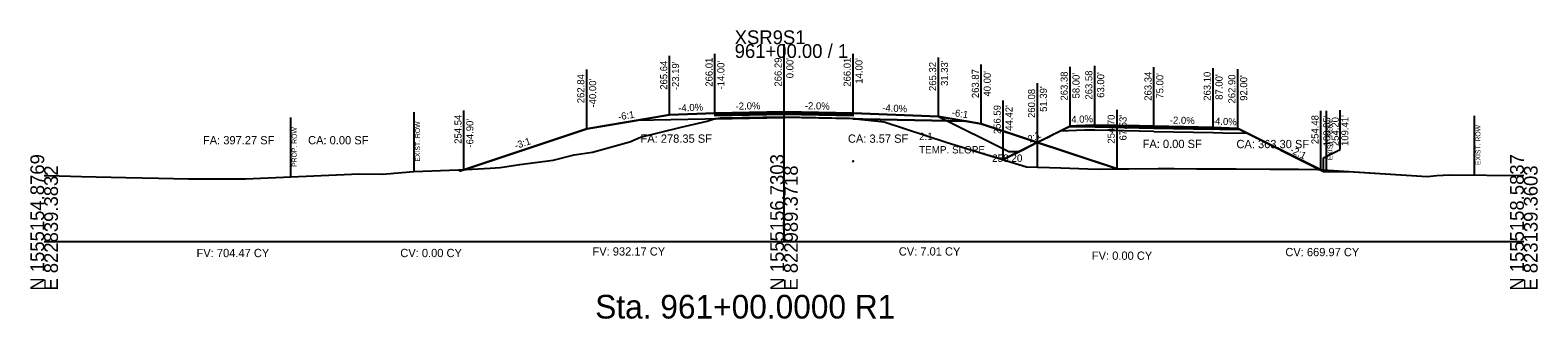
# Model space of a CAD drawing. Extents: x -26 to 823017, y -16 to 1558356.
# Drawn here: x 997.2 to 1302.8, y -15.7 to 42.8 of the extents above; entities that cross this region are included whole.
import ezdxf

# ---------------------------------------------------------------- set-up
doc = ezdxf.new("R2010")
doc.units = 0
for name, color, linetype in [('ASPHALT_19MM1', 7, 'Continuous'), ('ASPHALT_9_5MM1', 7, 'Continuous'), ('CONST_DCH', 7, 'Continuous'), ('CONST_LV3', 7, 'Continuous'), ('Default', 7, 'Continuous'), ('Draft_XS_Grid', 7, 'Continuous'), ('Draft_XS_Text', 7, 'Continuous'), ('DTM_CORRIDOR', 7, 'Continuous'), ('DTM_P_FINISHED_GRADE2', 7, 'Continuous'), ('DTM_TEMP_DROP', 7, 'Continuous'), ('DTM_X_GROUND', 7, 'Continuous'), ('PROFILES_DCH_2', 7, 'Continuous'), ('SLOPE_STAKES_FILL', 7, 'Continuous'), ('XS_CELL', 7, 'Continuous'), ('XS_M_SHAPES_EARTHWORK', 7, 'Continuous'), ('XS_P_ASPHALT', 7, 'Continuous'), ('XS_P_DR_GRAVEL', 7, 'Continuous'), ('XS_P_GROUND', 7, 'Continuous'), ('XS_P_NULL_POINT', 7, 'Continuous'), ('XS_P_ROW', 7, 'Continuous'), ('XS_P_SHOULDER', 7, 'Continuous'), ('XS_P_SUBGRADE_GRANULAR', 7, 'Continuous'), ('XS_P_SUBGRADE_MILLING', 7, 'Continuous'), ('XS_P_SUBGRADE_UNDERCUT', 7, 'Continuous'), ('XS_P_TX_CLEARZONE', 7, 'Continuous'), ('XS_P_TX_FS_BS', 7, 'Continuous'), ('XS_SHEET_EW_TX_AREA', 7, 'Continuous'), ('XS_SHEET_EW_TX_VOLUME', 7, 'Continuous'), ('XS_SHEET_LABELS_ELEVATION', 7, 'Continuous'), ('XS_X_ROW', 7, 'Continuous')]:
    doc.layers.add(name, color=color, linetype=linetype)

msp = doc.modelspace()

# ---------------------------------------------------------------- linework, layer by layer
at = {"layer": 'ASPHALT_19MM1'}
for points in [[(1136, 25.72), (1136, 25.51), (1150, 25.79), (1150, 25.79), (1150, 25.79), (1164, 25.51), (1164, 25.72), (1164, 25.72), (1150, 26), (1150, 26), (1150, 26), (1136, 25.72), (1136, 25.72)], [(1213, 23.21), (1225, 22.97), (1237, 22.73), (1237, 22.94), (1225, 23.18), (1213, 23.42), (1213, 23.21)]]:
    msp.add_lwpolyline(points, dxfattribs=at)
at = {"layer": 'ASPHALT_9_5MM1'}
msp.add_lwpolyline([(1136, 26.01), (1136, 25.89), (1150, 26.17), (1150, 26.17), (1150, 26.17), (1164, 25.89), (1164, 26.01), (1164, 26.01), (1150, 26.29), (1150, 26.29), (1150, 26.29), (1136, 26.01), (1136, 26.01)], dxfattribs=at)
at = {"layer": 'CONST_DCH'}
msp.add_lwpolyline([(1213, 23.42), (1225, 23.18), (1237, 22.94), (1237, 23.1), (1225, 23.34), (1213, 23.58), (1213, 23.42)], dxfattribs=at)
at = {"layer": 'CONST_LV3'}
for points in [[(1110, 22.84), (1110, 22.84), (1120.11, 24.53)], [(1150, 26.29), (1164, 26.01)], [(1181.33, 25.32), (1181.33, 25.32), (1164, 26.01)], [(1190, 23.87), (1190, 23.87), (1186.92, 24.39)], [(1194.42, 16.59), (1204.8, 21.78), (1208, 23.38), (1211.75, 23.53), (1213, 23.58)], [(1201.39, 20.08), (1201.42, 20.09), (1203.67, 21.22), (1204.46, 21.61), (1204.8, 21.78), (1205.55, 22.16), (1208, 23.38), (1209.25, 23.43), (1213, 23.58), (1222.01, 23.4), (1225, 23.34), (1234.01, 23.16), (1237, 23.1), (1240.75, 22.95), (1242, 22.9), (1246.15, 20.83), (1251.38, 18.21), (1257.12, 15.34), (1259.41, 14.2), (1265.44, 14.12), (1280.4, 13.18), (1282.33, 13.33), (1284.96, 13.52), (1300, 13.39)], [(1242, 22.9), (1258.85, 14.48)], [(1164, 16.06), (1164, 16.3), (1164, 16.24), (1164, 16.18), (1164, 16.18), (1164, 16.18), (1164, 16.18)], [(1000, 13.37), (1000.78, 13.37), (1007.55, 13.13), (1016.59, 12.94), (1023.15, 12.81), (1029.26, 12.71), (1034.76, 12.71), (1040.83, 12.71), (1063.85, 13.72), (1068.63, 13.65), (1069.41, 13.72), (1074.93, 14.18), (1082.17, 14.44), (1083.98, 14.51), (1084.36, 14.52), (1084.4, 14.52), (1084.58, 14.52), (1085.1, 14.54)]]:
    msp.add_lwpolyline(points, dxfattribs=at)
at = {"layer": 'Default'}
msp.add_lwpolyline([(1136, 25.89), (1136, 25.72), (1150, 26), (1150, 26), (1150, 26), (1164, 25.72), (1164, 25.89), (1164, 25.89), (1150, 26.17), (1150, 26.17), (1150, 26.17), (1136, 25.89), (1136, 25.89)], dxfattribs=at)
at = {"layer": 'DTM_P_FINISHED_GRADE2'}
msp.add_lwpolyline([(1085.1, 14.54), (1085.1, 14.54), (1110, 22.84), (1126.81, 25.64), (1136, 26.01), (1150, 26.29), (1164, 26.01), (1181.33, 25.32), (1190, 23.87), (1201.39, 20.08)], dxfattribs=at)
at = {"layer": 'DTM_X_GROUND'}
for points in [[(1000, 13.37), (1000.78, 13.37), (1007.55, 13.13), (1016.59, 12.94), (1023.15, 12.81), (1029.26, 12.71), (1034.76, 12.71), (1040.83, 12.71), (1063.85, 13.72), (1068.63, 13.65), (1069.41, 13.72), (1074.93, 14.18), (1082.17, 14.42), (1083.98, 14.5), (1084.36, 14.29), (1084.4, 14.31), (1084.58, 14.37), (1085.1, 14.54), (1085.1, 14.54), (1110, 22.84), (1110, 22.84), (1126.81, 25.64), (1126.81, 25.64), (1136, 26.01), (1150, 26.29), (1150, 26.29), (1150, 26.29), (1164, 26.01), (1181.33, 25.32), (1181.33, 25.32), (1190, 23.87), (1190, 23.87), (1201.39, 20.08), (1201.39, 20.08), (1201.42, 20.09), (1203.67, 21.22), (1204.46, 21.61), (1204.8, 21.78), (1205.55, 22.16), (1208, 23.38), (1209.25, 23.43), (1213, 23.58), (1222.01, 23.4), (1225, 23.34), (1234.01, 23.16), (1237, 23.1), (1240.75, 22.95), (1242, 22.9), (1246.15, 20.83), (1251.38, 18.21), (1257.12, 15.34), (1259.41, 14.2), (1265.44, 14.12), (1280.4, 13.18), (1282.33, 13.33), (1284.96, 13.52), (1300, 13.39)], [(1000, 13.37), (1000.78, 13.37), (1007.55, 13.13), (1016.59, 12.94), (1023.15, 12.81), (1029.26, 12.71), (1034.76, 12.71), (1040.83, 12.71), (1063.85, 13.72), (1068.63, 13.65), (1069.41, 13.72), (1074.93, 14.18), (1083.98, 14.51), (1084.58, 14.52), (1085.58, 14.56), (1090.42, 14.85), (1092.46, 14.96), (1096.47, 15.62), (1103.19, 16.48), (1107.43, 17.54), (1111.15, 18.12), (1118.48, 20.14), (1118.73, 20.19), (1120.89, 21.15), (1129.17, 23.13), (1134.43, 24.39), (1135.61, 24.76), (1137.15, 25.03), (1137.35, 25.06), (1149.97, 25.23), (1150.12, 25.23), (1162.93, 24.98), (1163, 24.98), (1163.26, 24.96), (1170.31, 24.23), (1183.08, 20.08), (1184.63, 19.57), (1187.19, 18.79), (1199.14, 15.15), (1206.1, 14.92), (1211.6, 14.73), (1213.98, 14.65), (1225.91, 14.81), (1229.13, 14.77), (1254.32, 14.61), (1258.26, 14.57), (1280.4, 13.18), (1282.33, 13.33), (1284.96, 13.52), (1300, 13.39)], [(1000, 13.37), (1000.78, 13.37), (1007.55, 13.13), (1016.59, 12.94), (1023.15, 12.81), (1029.26, 12.71), (1034.76, 12.71), (1040.83, 12.71), (1063.85, 13.72), (1068.63, 13.65), (1069.41, 13.72), (1074.93, 14.18), (1083.98, 14.51), (1084.58, 14.52), (1085.58, 14.56), (1090.42, 14.85), (1092.46, 14.96), (1096.47, 15.62), (1103.19, 16.48), (1107.43, 17.54), (1111.15, 18.12), (1118.48, 20.14), (1118.73, 20.19), (1120.89, 21.15), (1129.17, 23.13), (1134.43, 24.39), (1135.61, 24.76), (1137.15, 25.03), (1137.35, 25.06), (1149.97, 25.23), (1150.12, 25.23), (1162.93, 24.98), (1163, 24.98), (1163.26, 24.96), (1170.31, 24.23), (1183.08, 20.08), (1184.63, 19.57), (1185.99, 19.16), (1187.19, 18.79), (1194.42, 16.59), (1198.84, 18.8), (1201.42, 20.09), (1203.67, 21.22), (1204.46, 21.61), (1204.8, 21.78), (1208, 23.38), (1209.25, 23.43), (1213, 23.58), (1222.01, 23.4), (1225, 23.34), (1234.01, 23.16), (1237, 23.1), (1240.75, 22.95), (1242, 22.9), (1246.15, 20.83), (1251.38, 18.21), (1257.12, 15.34), (1259.41, 14.2), (1265.44, 14.12), (1280.4, 13.18), (1282.33, 13.33), (1284.96, 13.52), (1300, 13.39)]]:
    msp.add_lwpolyline(points, dxfattribs=at)
at = {"layer": 'XS_CELL'}
for p, q in [((1150, 0), (1150, 40)), ((1000, 0), (1150, 0)), ((1150, 0), (1300, 0))]:
    msp.add_line(p, q, dxfattribs=at)
at = {"layer": 'XS_M_SHAPES_EARTHWORK'}
for points in [[(1085.1, 14.54), (1085.58, 14.56), (1090.42, 14.85), (1092.46, 14.96), (1096.47, 15.62), (1103.19, 16.48), (1107.43, 17.54), (1111.15, 18.12), (1118.48, 20.14), (1118.73, 20.19), (1120.89, 21.15), (1129.17, 23.13), (1134.43, 24.39), (1135.61, 24.76), (1136.09, 24.85), (1136, 24.84), (1134, 24.8), (1120.11, 24.53), (1110, 22.84)], [(1136.09, 24.85), (1137.15, 25.03), (1137.35, 25.06), (1149.97, 25.23), (1150.12, 25.23), (1162.93, 24.98), (1163, 24.98), (1163.26, 24.96), (1164.42, 24.84), (1164, 24.84), (1150, 25.12)], [(1164.42, 24.84), (1170.31, 24.23), (1183.08, 20.08), (1184.63, 19.57), (1187.19, 18.79), (1199.14, 15.15), (1201.39, 15.08), (1201.39, 20.08), (1190, 23.87), (1186.92, 24.39), (1166, 24.8)]]:
    msp.add_lwpolyline(points, close=True, dxfattribs=at)
at = {"layer": 'XS_P_DR_GRAVEL'}
for points in [[(1211.75, 23.53), (1208, 23.38), (1207.96, 23.36), (1207.86, 23.31), (1209.14, 23.28), (1213, 23.21), (1213, 23.49), (1213, 23.58), (1211.75, 23.53)], [(1238.25, 23.05), (1242, 22.9), (1242.14, 22.83), (1242.57, 22.62), (1238.39, 22.7), (1237, 22.73), (1237, 23.01), (1237, 23.1), (1238.25, 23.05)]]:
    msp.add_lwpolyline(points, dxfattribs=at)
at = {"layer": 'XS_P_GROUND'}
for p, q in [((1181.33, 25.32), (1195.56, 18.2)), ((1195.56, 18.2), (1197.64, 18.2))]:
    msp.add_line(p, q, dxfattribs=at)
for points in [[(1126.81, 25.64), (1110, 22.84), (1085.1, 14.54)], [(1201.39, 20.08), (1201.39, 20.08), (1190, 23.87), (1190, 23.87), (1181.33, 25.32)], [(1217.53, 14.7), (1190, 23.87), (1190, 23.87), (1190, 23.87), (1181.33, 25.32)], [(1208, 23.38), (1194.42, 16.59)], [(1242, 22.9), (1259.41, 14.2)], [(1217.53, 14.7), (1217.53, 14.7), (1225.91, 14.81), (1225.91, 14.81), (1229.13, 14.77), (1254.32, 14.61), (1254.32, 14.61), (1258.26, 14.57), (1258.85, 14.53)], [(1217.53, 14.7), (1217.53, 14.7), (1225.91, 14.81), (1225.91, 14.81), (1229.13, 14.77), (1254.32, 14.61), (1254.32, 14.61), (1258.26, 14.57), (1258.85, 14.53)]]:
    msp.add_lwpolyline(points, dxfattribs=at)
at = {"layer": 'XS_P_ROW'}
msp.add_line((1050, 13.11), (1050, 25.11), dxfattribs=at)
at = {"layer": 'XS_P_SHOULDER'}
for points in [[(1136, 26.01), (1126.81, 25.64)], [(1164, 26.01), (1181.33, 25.32)], [(1208, 23.38), (1211.75, 23.53), (1213, 23.58)], [(1242, 22.9), (1238.25, 23.05), (1237, 23.1)]]:
    msp.add_lwpolyline(points, dxfattribs=at)
at = {"layer": 'XS_P_SUBGRADE_GRANULAR'}
for points in [[(1136, 24.84), (1134, 24.8), (1120.11, 24.53)], [(1136, 24.84), (1150, 25.12), (1150, 25.12)], [(1164, 24.84), (1150, 25.12), (1150, 25.12)], [(1164, 24.84), (1166, 24.8), (1186.92, 24.39)], [(1213, 22.54), (1211, 22.58), (1206, 22.38)], [(1225, 22.3), (1213, 22.54)], [(1225, 22.3), (1237, 22.06)], [(1237, 22.06), (1239, 22.02), (1243.96, 21.92)]]:
    msp.add_lwpolyline(points, dxfattribs=at)
at = {"layer": 'XS_P_SUBGRADE_UNDERCUT'}
msp.add_lwpolyline([(1217.59, 14.72), (1225.91, 14.81), (1233.71, 14.74), (1248.47, 14.65), (1258.7, 14.56), (1242, 22.9), (1237, 23.1), (1234.01, 23.16), (1225, 23.34), (1222.01, 23.4), (1213, 23.58), (1209.25, 23.43), (1208, 23.38), (1201.39, 20.08)], close=True, dxfattribs=at)
at = {"layer": 'XS_P_TX_CLEARZONE'}
for p, q in [((1126.81, 25.64), (1126.81, 37.64)), ((1136, 26.01), (1136, 38.01)), ((1150, 26.29), (1150, 38.29)), ((1164, 26.01), (1164, 38.01)), ((1181.33, 25.32), (1181.33, 37.32)), ((1110, 22.84), (1110, 34.84)), ((1190, 23.87), (1190, 35.87)), ((1190, 23.87), (1190, 35.87)), ((1208, 23.38), (1208, 35.38)), ((1213, 23.58), (1213, 35.58)), ((1225, 23.34), (1225, 35.34)), ((1237, 23.1), (1237, 35.1)), ((1242, 22.9), (1242, 34.9)), ((1201.39, 20.08), (1201.39, 32.08)), ((1194.42, 16.59), (1194.42, 28.59)), ((1085.1, 14.54), (1085.1, 26.54)), ((1217.53, 14.7), (1217.53, 26.7)), ((1258.85, 14.48), (1258.85, 26.48)), ((1262.74, 18.66), (1262.74, 26.61)), ((1259.41, 16.91), (1262.74, 18.66)), ((1259.41, 14.2), (1259.41, 16.91))]:
    msp.add_line(p, q, dxfattribs=at)
at = {"layer": 'XS_X_ROW'}
for p, q in [((1075, 14.19), (1075, 26.19)), ((1260, 14.46), (1260, 26.46)), ((1290, 13.48), (1290, 25.48))]:
    msp.add_line(p, q, dxfattribs=at)

# ---------------------------------------------------------------- texts
at = {"layer": 'CONST_DCH'}
for p in [(1194.34, 16.47), (1258.77, 14.36), (1259.34, 14.08)]:
    msp.add_text('X', height=0.24, dxfattribs=at).set_placement(p)
at = {"layer": 'Draft_XS_Grid'}
msp.add_text('-', height=0.0001, dxfattribs=at).set_placement((1000, 0))
at = {"layer": 'Draft_XS_Text'}
msp.add_text('Sta. 961+00.0000 R1', height=4.8, dxfattribs=at).set_placement((1111.72, -15.65))
at = {"layer": 'DTM_CORRIDOR'}
for p in [(1212.92, 23.46), (1224.92, 23.22), (1236.92, 22.98)]:
    msp.add_text('X', height=0.24, dxfattribs=at).set_placement(p)
at = {"layer": 'DTM_TEMP_DROP'}
for p in [(1135.92, 25.89), (1149.92, 26.17), (1163.92, 25.89)]:
    msp.add_text('X', height=0.24, dxfattribs=at).set_placement(p)
at = {"layer": 'PROFILES_DCH_2'}
for p in [(1181.25, 25.2), (1189.92, 23.75), (1217.45, 14.58), (1258.77, 14.36)]:
    msp.add_text('X', height=0.24, dxfattribs=at).set_placement(p)
at = {"layer": 'SLOPE_STAKES_FILL'}
for p in [(1201.31, 19.96), (1085.02, 14.42)]:
    msp.add_text('X', height=0.24, dxfattribs=at).set_placement(p)
at = {"layer": 'XS_CELL'}
for s, p in [('XSR9S1', (1140, 40)), ('961+00.00 / 1', (1140, 37.2))]:
    msp.add_text(s, height=2.8, dxfattribs=at).set_placement(p)
for s, p in [('N 1555154.8769', (1000, -10)), ('N 1555156.7303', (1150, -10)), ('N 1555158.5837', (1300, -10)), ('E 822839.3832', (1002.8, -10)), ('E 822989.3718', (1152.8, -10)), ('E 823139.3603', (1302.8, -10))]:
    msp.add_text(s, height=2.8, rotation=90, dxfattribs=at).set_placement(p)
at = {"layer": 'XS_P_ASPHALT'}
for p in [(1194.34, 16.47), (1259.34, 14.08)]:
    msp.add_text('X', height=0.24, dxfattribs=at).set_placement(p)
at = {"layer": 'XS_P_GROUND'}
for s, p in [('2:1', (1177.38, 20.53)), ('TEMP. SLOPE', (1177.38, 17.83))]:
    msp.add_text(s, height=1.5, dxfattribs=at).set_placement(p)
at = {"layer": 'XS_P_NULL_POINT'}
for p in [(1201.31, 19.96), (1085.02, 14.42)]:
    msp.add_text('X', height=0.24, dxfattribs=at).set_placement(p)
at = {"layer": 'XS_P_ROW'}
msp.add_text('PROP. ROW', height=1, rotation=90, dxfattribs=at).set_placement((1051.2, 15.11))
at = {"layer": 'XS_P_SHOULDER'}
for p in [(1109.92, 22.72), (1189.92, 23.75), (1207.92, 23.26), (1241.92, 22.78)]:
    msp.add_text('X', height=0.24, dxfattribs=at).set_placement(p)
at = {"layer": 'XS_P_SUBGRADE_MILLING'}
for p in [(1126.73, 25.52), (1181.25, 25.2)]:
    msp.add_text('X', height=0.24, dxfattribs=at).set_placement(p)
at = {"layer": 'XS_P_TX_CLEARZONE'}
for s, p in [('266.01', (1135.52, 31.37)), ('266.29', (1149.52, 31.39)), ("0.00'", (1151.92, 33.08)), ('266.01', (1163.52, 31.37)), ("14.00'", (1165.92, 31.98)), ('262.84', (1109.52, 28.02)), ('265.64', (1126.33, 30.75)), ("-23.19'", (1128.73, 30.66)), ("-14.00'", (1137.92, 30.8)), ('265.32', (1180.85, 30.5)), ("31.33'", (1183.25, 31.52)), ('263.87', (1189.52, 29.05)), ("40.00'", (1191.92, 29.37)), ('263.38', (1207.52, 28.56)), ("58.00'", (1209.92, 28.99)), ('263.58', (1212.52, 28.76)), ("63.00'", (1214.92, 29.12)), ('263.34', (1224.52, 28.52)), ("75.00'", (1226.92, 28.95)), ('263.10', (1236.52, 28.52)), ("87.00'", (1238.92, 28.71)), ('262.90', (1241.52, 27.96)), ("-40.00'", (1111.92, 27.16)), ('260.08', (1200.91, 25.03)), ("51.39'", (1203.31, 26.27)), ("92.00'", (1243.92, 28.51)), ('256.59', (1193.94, 21.76)), ("44.42'", (1196.34, 22.43)), ('254.54', (1084.62, 19.79)), ("-64.90'", (1087.02, 19.02)), ('254.70', (1217.05, 19.82)), ("67.53'", (1219.45, 20.46)), ('254.48', (1258.37, 19.72)), ("108.85'", (1260.77, 19.27)), ('254.20', (1262.48, 19.32)), ("109.41'", (1264.43, 19.35))]:
    msp.add_text(s, height=1.44, rotation=90, dxfattribs=at).set_placement(p)
at = {"layer": 'XS_P_TX_FS_BS'}
for s, rotation, p in [('-4.0%', 2.2906, (1128.59, 26.32)), ('-2.0%', 1.1458, (1140.2, 26.7)), ('-2.0%', 358.8542, (1154.22, 26.81)), ('-4.0%', 357.7094, (1169.9, 26.38)), ('-6:1', 9.4642, (1116.48, 24.53)), ('-6:1', 350.5358, (1183.94, 25.49)), ('4.0%', 2.2906, (1208.27, 23.99)), ('-2.0%', 358.8542, (1228.22, 23.88)), ('-4.0%', 357.7094, (1236.73, 23.71)), ('2:1', 26.5651, (1199.85, 19.98)), ('-3:1', 18.4332, (1095.64, 18.69)), ('-2:1', 333.4349, (1252.46, 18.09))]:
    msp.add_text(s, height=1.44, rotation=rotation, dxfattribs=at).set_placement(p)
at = {"layer": 'XS_SHEET_EW_TX_AREA'}
for s, p in [('FA: 278.35 SF', (1120.91, 20)), ('CA: 3.57 SF', (1162.96, 20)), ('FA: 397.27 SF', (1032.19, 19.68)), ('CA: 0.00 SF', (1053.51, 19.68)), ('FA: 0.00 SF', (1222.71, 18.93)), ('CA: 363.30 SF', (1241.73, 18.9))]:
    msp.add_text(s, height=1.68, dxfattribs=at).set_placement(p)
at = {"layer": 'XS_SHEET_EW_TX_VOLUME'}
for s, p in [('FV: 704.47 CY', (1030.9, -3.2)), ('CV: 0.00 CY', (1072.21, -3.2)), ('FV: 932.17 CY', (1111.17, -2.88)), ('CV: 7.01 CY', (1173.27, -2.88)), ('FV: 0.00 CY', (1212.42, -3.74)), ('CV: 669.97 CY', (1251.65, -3.01))]:
    msp.add_text(s, height=1.68, dxfattribs=at).set_placement(p)
at = {"layer": 'XS_SHEET_LABELS_ELEVATION'}
msp.add_text('258.20', height=1.5, dxfattribs=at).set_placement((1192.2, 16.12))
at = {"layer": 'XS_X_ROW'}
for p in [(1076.2, 16.19), (1261.2, 16.46), (1291.2, 15.48)]:
    msp.add_text('EXIST. ROW', height=1, rotation=90, dxfattribs=at).set_placement(p)

doc.saveas('drawing.dxf')
